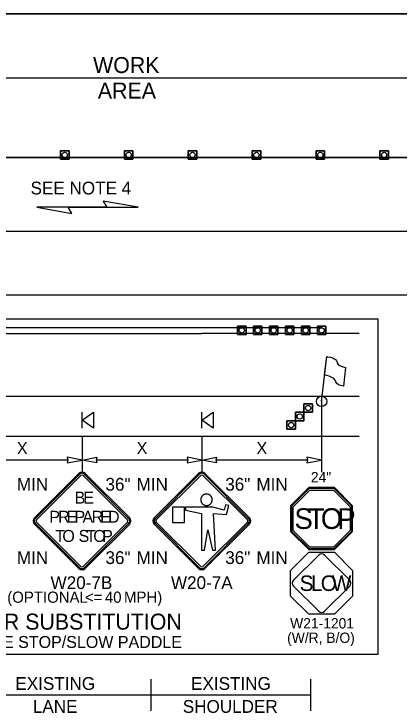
# Model space of a CAD drawing. Extents: x 99999.1 to 100095.7, y 99995 to 100010.7.
# Drawn here: x 100006.832 to 100009.243, y 100003.112 to 100007.492 of the extents above; entities that cross this region are included whole.
import ezdxf

# ---------------------------------------------------------------- set-up
doc = ezdxf.new("R2010")
doc.units = 0
for name, color, linetype in [('RD_ED_ShoulderPavedEdge', 7, 'Continuous'), ('RD_MK_LineDblYellowCenter', 7, 'Continuous'), ('RD_MK_LineEdgeWhite', 7, 'Continuous'), ('RD_MK_LineNoPass', 7, 'Continuous'), ('RD_MK_LineSkipCenter', 7, 'Continuous'), ('SH_DE_DetailHeading2Text', 7, 'Continuous'), ('TR_SN_ConstructionSigns', 7, 'Continuous'), ('TR_WZ_FlaggingStation', 7, 'Continuous'), ('TR_WZ_PortableSignMountBlk-Org', 7, 'Continuous'), ('TR_WZ_TrafficCone', 7, 'Continuous'), ('TR_WZ_WorkAreaLabel', 7, 'Continuous'), ('TR_WZ_WorkZoneDetails', 7, 'Continuous'), ('TR_WZ_WorkZoneTextCurrent', 7, 'Continuous')]:
    doc.layers.add(name, color=color, linetype=linetype)

msp = doc.modelspace()

# ---------------------------------------------------------------- linework, layer by layer
at = {"layer": 'RD_ED_ShoulderPavedEdge'}
for p, q in [((100000.1076, 100007.4923), (100015.6424, 100007.4923)), ((100000.1076, 100005.7323), (100015.6424, 100005.7323)), ((100005.4994, 100004.8473), (100008.9925, 100004.8473))]:
    msp.add_line(p, q, dxfattribs=at)
at = {"layer": 'RD_MK_LineDblYellowCenter'}
for p, q in [((100005.4994, 100005.5286), (100008.0081, 100005.5286)), ((100005.4994, 100005.4911), (100008.0081, 100005.4911))]:
    msp.add_line(p, q, dxfattribs=at)
at = {"layer": 'RD_MK_LineEdgeWhite'}
for p, q in [((100000.1076, 100007.0923), (100015.6424, 100007.0923)), ((100000.1076, 100006.1323), (100015.6424, 100006.1323)), ((100005.4994, 100005.0973), (100008.9925, 100005.0973))]:
    msp.add_line(p, q, dxfattribs=at)
at = {"layer": 'RD_MK_LineNoPass'}
msp.add_line((100008.0081, 100005.5286), (100008.7581, 100005.5286), dxfattribs=at)
at = {"layer": 'RD_MK_LineSkipCenter'}
for points in [[(100011.15, 100006.5923), (100003.4767, 100006.5923)], [(100008.9925, 100005.4911), (100008.0081, 100005.4911)]]:
    msp.add_lwpolyline(points, dxfattribs=at)
at = {"layer": 'TR_SN_ConstructionSigns'}
for p, q in [((100007.2382, 100004.6141), (100006.9598, 100004.3357)), ((100007.2437, 100004.6086), (100006.9653, 100004.3301)), ((100006.973, 100004.3224), (100007.2515, 100004.6008)), ((100007.2647, 100004.6008), (100007.5431, 100004.3224)), ((100007.5509, 100004.3301), (100007.2724, 100004.6086)), ((100007.5564, 100004.3357), (100007.278, 100004.6141)), ((100007.9882, 100004.6141), (100007.7098, 100004.3357)), ((100007.9937, 100004.6086), (100007.7153, 100004.3301)), ((100007.723, 100004.3224), (100008.0015, 100004.6008)), ((100008.0147, 100004.6008), (100008.2931, 100004.3224)), ((100008.3009, 100004.3301), (100008.0224, 100004.6086)), ((100008.3064, 100004.3357), (100008.028, 100004.6141)), ((100008.6775, 100004.5251), (100008.5636, 100004.4113)), ((100008.68, 100004.5191), (100008.5697, 100004.4087)), ((100008.5798, 100004.4046), (100008.6842, 100004.5089)), ((100008.8385, 100004.5251), (100008.6775, 100004.5251)), ((100008.836, 100004.5191), (100008.68, 100004.5191)), ((100008.6842, 100004.5089), (100008.8318, 100004.5089)), ((100008.8318, 100004.5089), (100008.9362, 100004.4046)), ((100008.9463, 100004.4087), (100008.836, 100004.5191)), ((100008.9524, 100004.4113), (100008.8385, 100004.5251)), ((100008.0015, 100004.4523), (100008.0013, 100004.4504)), ((100008.0013, 100004.4504), (100008.0013, 100004.4485)), ((100008.0013, 100004.4485), (100008.0013, 100004.4466)), ((100008.0013, 100004.4466), (100008.0015, 100004.4447)), ((100008.0017, 100004.4543), (100008.0015, 100004.4523)), ((100008.0021, 100004.4561), (100008.0017, 100004.4543)), ((100008.0025, 100004.458), (100008.0021, 100004.4561)), ((100008.0031, 100004.4598), (100008.0025, 100004.458)), ((100008.0037, 100004.4616), (100008.0031, 100004.4598)), ((100008.0045, 100004.4634), (100008.0037, 100004.4616)), ((100008.0053, 100004.4651), (100008.0045, 100004.4634)), ((100008.0062, 100004.4668), (100008.0053, 100004.4651)), ((100008.0073, 100004.4685), (100008.0062, 100004.4668)), ((100008.0083, 100004.47), (100008.0073, 100004.4685)), ((100008.0095, 100004.4715), (100008.0083, 100004.47)), ((100008.0108, 100004.473), (100008.0095, 100004.4715)), ((100008.0122, 100004.4743), (100008.0108, 100004.473)), ((100008.0135, 100004.4756), (100008.0122, 100004.4743)), ((100008.015, 100004.4768), (100008.0135, 100004.4756)), ((100008.0165, 100004.478), (100008.015, 100004.4768)), ((100008.0182, 100004.479), (100008.0165, 100004.478)), ((100008.0198, 100004.48), (100008.0182, 100004.479)), ((100008.0215, 100004.4809), (100008.0198, 100004.48)), ((100008.0232, 100004.4817), (100008.0215, 100004.4809)), ((100008.025, 100004.4824), (100008.0232, 100004.4817)), ((100008.0269, 100004.483), (100008.025, 100004.4824)), ((100008.0287, 100004.4835), (100008.0269, 100004.483)), ((100008.0306, 100004.4839), (100008.0287, 100004.4835)), ((100008.0325, 100004.4842), (100008.0306, 100004.4839)), ((100008.0344, 100004.4844), (100008.0325, 100004.4842)), ((100008.0363, 100004.4845), (100008.0344, 100004.4844)), ((100008.0382, 100004.4845), (100008.0363, 100004.4845)), ((100008.0401, 100004.4844), (100008.0382, 100004.4845)), ((100008.0421, 100004.4842), (100008.0401, 100004.4844)), ((100008.0439, 100004.4839), (100008.0421, 100004.4842)), ((100008.0458, 100004.4835), (100008.0439, 100004.4839)), ((100008.0476, 100004.483), (100008.0458, 100004.4835)), ((100008.0495, 100004.4824), (100008.0476, 100004.483)), ((100008.0513, 100004.4817), (100008.0495, 100004.4824)), ((100008.053, 100004.4809), (100008.0513, 100004.4817)), ((100008.0547, 100004.48), (100008.053, 100004.4809)), ((100008.0564, 100004.479), (100008.0547, 100004.48)), ((100008.058, 100004.478), (100008.0564, 100004.479)), ((100008.0595, 100004.4768), (100008.058, 100004.478)), ((100008.061, 100004.4756), (100008.0595, 100004.4768)), ((100008.0624, 100004.4743), (100008.061, 100004.4756)), ((100008.0637, 100004.473), (100008.0624, 100004.4743)), ((100008.065, 100004.4715), (100008.0637, 100004.473)), ((100008.0661, 100004.47), (100008.065, 100004.4715)), ((100008.0673, 100004.4685), (100008.0661, 100004.47)), ((100008.0683, 100004.4668), (100008.0673, 100004.4685)), ((100008.0692, 100004.4651), (100008.0683, 100004.4668)), ((100008.07, 100004.4634), (100008.0692, 100004.4651)), ((100008.0708, 100004.4616), (100008.07, 100004.4634)), ((100008.0715, 100004.4598), (100008.0708, 100004.4616)), ((100008.072, 100004.458), (100008.0715, 100004.4598)), ((100008.0725, 100004.4561), (100008.072, 100004.458)), ((100008.0728, 100004.4543), (100008.0725, 100004.4561)), ((100008.0731, 100004.4523), (100008.0728, 100004.4543)), ((100008.0732, 100004.4504), (100008.0731, 100004.4523)), ((100008.0731, 100004.4447), (100008.0732, 100004.4466)), ((100008.0733, 100004.4485), (100008.0732, 100004.4504)), ((100008.0732, 100004.4466), (100008.0733, 100004.4485)), ((100008.0015, 100004.4447), (100008.0017, 100004.4428)), ((100008.0017, 100004.4428), (100008.0021, 100004.4409)), ((100008.0021, 100004.4409), (100008.0025, 100004.439)), ((100008.0025, 100004.439), (100008.0031, 100004.4372)), ((100008.0031, 100004.4372), (100008.0037, 100004.4354)), ((100008.0037, 100004.4354), (100008.0045, 100004.4336)), ((100008.0045, 100004.4336), (100008.0053, 100004.4319)), ((100008.0053, 100004.4319), (100008.0062, 100004.4302)), ((100008.0062, 100004.4302), (100008.0073, 100004.4286)), ((100008.0073, 100004.4286), (100008.0083, 100004.427)), ((100008.0083, 100004.427), (100008.0095, 100004.4255)), ((100008.0095, 100004.4255), (100008.0108, 100004.4241)), ((100008.0108, 100004.4241), (100008.0122, 100004.4227)), ((100008.0122, 100004.4227), (100008.0135, 100004.4214)), ((100008.0135, 100004.4214), (100008.015, 100004.4202)), ((100008.015, 100004.4202), (100008.0165, 100004.419)), ((100008.0165, 100004.419), (100008.0182, 100004.418)), ((100008.0182, 100004.418), (100008.0198, 100004.417)), ((100008.0198, 100004.417), (100008.0215, 100004.4161)), ((100008.0215, 100004.4161), (100008.0232, 100004.4153)), ((100008.0232, 100004.4153), (100008.025, 100004.4146)), ((100008.025, 100004.4146), (100008.0269, 100004.414)), ((100008.0269, 100004.414), (100008.0287, 100004.4135)), ((100008.0287, 100004.4135), (100008.0306, 100004.4131)), ((100008.0306, 100004.4131), (100008.0325, 100004.4128)), ((100008.0325, 100004.4128), (100008.0344, 100004.4126)), ((100008.0344, 100004.4126), (100008.0363, 100004.4125)), ((100008.0363, 100004.4125), (100008.0382, 100004.4125)), ((100008.0382, 100004.4125), (100008.0401, 100004.4126)), ((100008.0401, 100004.4126), (100008.0421, 100004.4128)), ((100008.0421, 100004.4128), (100008.0439, 100004.4131)), ((100008.0439, 100004.4131), (100008.0458, 100004.4135)), ((100008.0458, 100004.4135), (100008.0476, 100004.414)), ((100008.0476, 100004.414), (100008.0495, 100004.4146)), ((100008.0495, 100004.4146), (100008.0513, 100004.4153)), ((100008.0513, 100004.4153), (100008.053, 100004.4161)), ((100008.053, 100004.4161), (100008.0547, 100004.417)), ((100008.0547, 100004.417), (100008.0564, 100004.418)), ((100008.0564, 100004.418), (100008.058, 100004.419)), ((100008.058, 100004.419), (100008.0595, 100004.4202)), ((100008.0595, 100004.4202), (100008.061, 100004.4214)), ((100008.061, 100004.4214), (100008.0624, 100004.4227)), ((100008.0624, 100004.4227), (100008.0637, 100004.4241)), ((100008.0637, 100004.4241), (100008.065, 100004.4255)), ((100008.065, 100004.4255), (100008.0661, 100004.427)), ((100008.0661, 100004.427), (100008.0673, 100004.4286)), ((100008.0673, 100004.4286), (100008.0683, 100004.4302)), ((100008.0683, 100004.4302), (100008.0692, 100004.4319)), ((100008.0692, 100004.4319), (100008.07, 100004.4336)), ((100008.07, 100004.4336), (100008.0708, 100004.4354)), ((100008.0708, 100004.4354), (100008.0715, 100004.4372)), ((100008.0715, 100004.4372), (100008.072, 100004.439)), ((100008.072, 100004.439), (100008.0725, 100004.4409)), ((100008.0725, 100004.4409), (100008.0728, 100004.4428)), ((100008.0728, 100004.4428), (100008.0731, 100004.4447)), ((100008.1568, 100004.4169), (100008.1471, 100004.3841)), ((100008.1767, 100004.4133), (100008.1568, 100004.4169)), ((100008.1617, 100004.3565), (100008.1767, 100004.4133)), ((100008.5636, 100004.4113), (100008.5636, 100004.2502)), ((100008.5697, 100004.4087), (100008.5697, 100004.2527)), ((100008.5798, 100004.2569), (100008.5798, 100004.4046)), ((100008.9362, 100004.4046), (100008.9362, 100004.2569)), ((100008.9463, 100004.2527), (100008.9463, 100004.4087)), ((100008.9524, 100004.2502), (100008.9524, 100004.4113)), ((100007.8238, 100004.4012), (100007.8238, 100004.3065)), ((100007.8992, 100004.4012), (100007.8238, 100004.4012)), ((100007.8992, 100004.3065), (100007.8992, 100004.4012)), ((100008.0775, 100004.4012), (100007.9062, 100004.4012)), ((100007.9062, 100004.4012), (100007.9062, 100004.3831)), ((100007.9062, 100004.3831), (100008.0057, 100004.3633)), ((100008.0057, 100004.3633), (100008.0057, 100004.133)), ((100008.1471, 100004.3841), (100008.0775, 100004.4012)), ((100008.0938, 100004.133), (100008.0807, 100004.3634)), ((100008.0807, 100004.3634), (100008.1617, 100004.3565)), ((100006.9598, 100004.2959), (100007.2382, 100004.0175)), ((100006.9653, 100004.3014), (100007.2437, 100004.023)), ((100007.2515, 100004.0307), (100006.973, 100004.3092)), ((100007.5431, 100004.3092), (100007.2647, 100004.0307)), ((100007.2724, 100004.023), (100007.5509, 100004.3014)), ((100007.278, 100004.0175), (100007.5564, 100004.2959)), ((100007.7098, 100004.2959), (100007.9882, 100004.0175)), ((100007.7153, 100004.3014), (100007.9937, 100004.023)), ((100008.0015, 100004.0307), (100007.723, 100004.3092)), ((100007.8238, 100004.3065), (100007.8992, 100004.3065)), ((100008.2931, 100004.3092), (100008.0147, 100004.0307)), ((100008.0224, 100004.023), (100008.3009, 100004.3014)), ((100008.028, 100004.0175), (100008.3064, 100004.2959)), ((100008.0259, 100004.133), (100008.0455, 100004.2597)), ((100008.0455, 100004.2597), (100008.0758, 100004.133)), ((100008.5636, 100004.2502), (100008.6775, 100004.1363)), ((100008.5697, 100004.2527), (100008.68, 100004.1424)), ((100008.6842, 100004.1525), (100008.5798, 100004.2569)), ((100008.9362, 100004.2569), (100008.8318, 100004.1525)), ((100008.836, 100004.1424), (100008.9463, 100004.2527)), ((100008.8385, 100004.1363), (100008.9524, 100004.2502)), ((100008.68, 100004.1424), (100008.836, 100004.1424)), ((100008.8318, 100004.1525), (100008.6842, 100004.1525)), ((100008.0057, 100004.133), (100008.0259, 100004.133)), ((100008.0758, 100004.133), (100008.0938, 100004.133)), ((100008.7397, 100004.1018), (100008.5819, 100003.9441)), ((100008.6775, 100004.1363), (100008.8385, 100004.1363)), ((100008.9341, 100003.9441), (100008.7763, 100004.1018)), ((100008.5819, 100003.9074), (100008.7397, 100003.7497)), ((100008.7763, 100003.7497), (100008.9341, 100003.9074))]:
    msp.add_line(p, q, dxfattribs=at)
msp.add_lwpolyline([(100008.9524, 100004.0063), (100008.9524, 100003.8452), (100008.8385, 100003.7313), (100008.6775, 100003.7313), (100008.5636, 100003.8452), (100008.5636, 100004.0063), (100008.6775, 100004.1201), (100008.8385, 100004.1201)], close=True, dxfattribs=at)
for centre, radius, start, end in [((100007.2581, 100004.5942), 0.0281, 45, 135), ((100008.0081, 100004.5942), 0.0281, 45, 135), ((100007.2581, 100004.5942), 0.0203, 45, 135), ((100007.2581, 100004.5942), 0.00937, 45, 135), ((100008.0081, 100004.5942), 0.0203, 45, 135), ((100008.0081, 100004.5942), 0.00937, 45, 135), ((100006.9797, 100004.3158), 0.0281, 135, 225), ((100006.9797, 100004.3158), 0.0203, 135, 225), ((100006.9797, 100004.3158), 0.00937, 135, 225), ((100007.5365, 100004.3158), 0.00937, 315, 45), ((100007.5365, 100004.3158), 0.0203, 315, 45), ((100007.5365, 100004.3158), 0.0281, 315, 45), ((100007.7297, 100004.3158), 0.0281, 135, 225), ((100007.7297, 100004.3158), 0.0203, 135, 225), ((100007.7297, 100004.3158), 0.00937, 135, 225), ((100008.2865, 100004.3158), 0.00937, 315, 45), ((100008.2865, 100004.3158), 0.0203, 315, 45), ((100008.2865, 100004.3158), 0.0281, 315, 45), ((100008.758, 100004.0835), 0.0259, 45, 135), ((100007.2581, 100004.0374), 0.0281, 225, 315), ((100007.2581, 100004.0374), 0.0203, 225, 315), ((100007.2581, 100004.0374), 0.00937, 225, 315), ((100008.0081, 100004.0374), 0.0281, 225, 315), ((100008.0081, 100004.0374), 0.0203, 225, 315), ((100008.0081, 100004.0374), 0.00937, 225, 315), ((100008.6003, 100003.9257), 0.0259, 135, 225), ((100008.9157, 100003.9257), 0.0259, 315, 45), ((100008.758, 100003.768), 0.0259, 225, 315)]:
    msp.add_arc(centre, radius, start, end, dxfattribs=at)
at = {"layer": 'TR_WZ_FlaggingStation'}
for p, q in [((100008.7581, 100005.0648), (100008.7901, 100005.3458)), ((100008.7771, 100005.2317), (100008.7902, 100005.3461)), ((100008.9081, 100005.2783), (100008.8948, 100005.1611)), ((100008.7771, 100005.2317), (100008.7771, 100005.2317))]:
    msp.add_line(p, q, dxfattribs=at)
for points in [[(100008.7902, 100005.3461), (100008.7959, 100005.3448), (100008.8137, 100005.3414), (100008.8276, 100005.3372), (100008.8372, 100005.3311), (100008.8458, 100005.3264), (100008.8515, 100005.3196), (100008.8557, 100005.3117), (100008.8562, 100005.3055), (100008.8616, 100005.2963), (100008.8724, 100005.2889), (100008.8848, 100005.2837), (100008.9081, 100005.2783)], [(100008.8948, 100005.1611), (100008.8867, 100005.1625), (100008.869, 100005.1671), (100008.8533, 100005.1776), (100008.8468, 100005.1882), (100008.8429, 100005.1985), (100008.8338, 100005.2094), (100008.8229, 100005.2156), (100008.8055, 100005.2227), (100008.7771, 100005.2317)]]:
    msp.add_lwpolyline(points, dxfattribs=at)
msp.add_circle((100008.7581, 100005.0648), 0.0325, dxfattribs=at)
at = {"layer": 'TR_WZ_PortableSignMountBlk-Org'}
for p, q in [((100007.2581, 100004.8974), (100007.2581, 100004.9974)), ((100008.0081, 100004.8974), (100008.0081, 100004.9974))]:
    msp.add_line(p, q, dxfattribs=at)
for points in [[(100007.2581, 100004.9473), (100007.3299, 100004.9974), (100007.3299, 100004.8974)], [(100008.0081, 100004.9473), (100008.0799, 100004.9974), (100008.0799, 100004.8974)]]:
    msp.add_lwpolyline(points, close=True, dxfattribs=at)
at = {"layer": 'TR_WZ_TrafficCone'}
for points in [[(100007.1234, 100006.6357), (100007.1767, 100006.6357), (100007.1767, 100006.5823), (100007.1234, 100006.5823), (100007.1234, 100006.6357)], [(100007.1234, 100006.5823), (100007.1767, 100006.5823), (100007.1767, 100006.6357), (100007.1234, 100006.6357), (100007.1234, 100006.5823)], [(100007.5234, 100006.6357), (100007.5767, 100006.6357), (100007.5767, 100006.5823), (100007.5234, 100006.5823), (100007.5234, 100006.6357)], [(100007.5234, 100006.5823), (100007.5767, 100006.5823), (100007.5767, 100006.6357), (100007.5234, 100006.6357), (100007.5234, 100006.5823)], [(100007.9234, 100006.6357), (100007.9767, 100006.6357), (100007.9767, 100006.5823), (100007.9234, 100006.5823), (100007.9234, 100006.6357)], [(100007.9234, 100006.5823), (100007.9767, 100006.5823), (100007.9767, 100006.6357), (100007.9234, 100006.6357), (100007.9234, 100006.5823)], [(100008.3234, 100006.6357), (100008.3767, 100006.6357), (100008.3767, 100006.5823), (100008.3234, 100006.5823), (100008.3234, 100006.6357)], [(100008.3234, 100006.5823), (100008.3767, 100006.5823), (100008.3767, 100006.6357), (100008.3234, 100006.6357), (100008.3234, 100006.5823)], [(100008.7234, 100006.6357), (100008.7767, 100006.6357), (100008.7767, 100006.5823), (100008.7234, 100006.5823), (100008.7234, 100006.6357)], [(100008.7234, 100006.5823), (100008.7767, 100006.5823), (100008.7767, 100006.6357), (100008.7234, 100006.6357), (100008.7234, 100006.5823)], [(100009.1234, 100006.6357), (100009.1767, 100006.6357), (100009.1767, 100006.5823), (100009.1234, 100006.5823), (100009.1234, 100006.6357)], [(100009.1234, 100006.5823), (100009.1767, 100006.5823), (100009.1767, 100006.6357), (100009.1234, 100006.6357), (100009.1234, 100006.5823)], [(100008.2848, 100005.5365), (100008.2314, 100005.5365), (100008.2314, 100005.4832), (100008.2848, 100005.4832), (100008.2848, 100005.5365)], [(100008.2848, 100005.4832), (100008.2314, 100005.4832), (100008.2314, 100005.5365), (100008.2848, 100005.5365), (100008.2848, 100005.4832)], [(100008.3848, 100005.5365), (100008.3314, 100005.5365), (100008.3314, 100005.4832), (100008.3848, 100005.4832), (100008.3848, 100005.5365)], [(100008.3848, 100005.4832), (100008.3314, 100005.4832), (100008.3314, 100005.5365), (100008.3848, 100005.5365), (100008.3848, 100005.4832)], [(100008.4848, 100005.5365), (100008.4314, 100005.5365), (100008.4314, 100005.4832), (100008.4848, 100005.4832), (100008.4848, 100005.5365)], [(100008.4848, 100005.4832), (100008.4314, 100005.4832), (100008.4314, 100005.5365), (100008.4848, 100005.5365), (100008.4848, 100005.4832)], [(100008.5848, 100005.5365), (100008.5314, 100005.5365), (100008.5314, 100005.4832), (100008.5848, 100005.4832), (100008.5848, 100005.5365)], [(100008.5848, 100005.4832), (100008.5314, 100005.4832), (100008.5314, 100005.5365), (100008.5848, 100005.5365), (100008.5848, 100005.4832)], [(100008.6848, 100005.5365), (100008.6314, 100005.5365), (100008.6314, 100005.4832), (100008.6848, 100005.4832), (100008.6848, 100005.5365)], [(100008.6848, 100005.4832), (100008.6314, 100005.4832), (100008.6314, 100005.5365), (100008.6848, 100005.5365), (100008.6848, 100005.4832)], [(100008.7848, 100005.5365), (100008.7314, 100005.5365), (100008.7314, 100005.4832), (100008.7848, 100005.4832), (100008.7848, 100005.5365)], [(100008.7848, 100005.4832), (100008.7314, 100005.4832), (100008.7314, 100005.5365), (100008.7848, 100005.5365), (100008.7848, 100005.4832)], [(100008.6474, 100005.05), (100008.7008, 100005.05), (100008.7008, 100004.9967), (100008.6474, 100004.9967), (100008.6474, 100005.05)], [(100008.6474, 100004.9967), (100008.7008, 100004.9967), (100008.7008, 100005.05), (100008.6474, 100005.05), (100008.6474, 100004.9967)], [(100008.5941, 100004.9967), (100008.6474, 100004.9967), (100008.6474, 100004.9433), (100008.5941, 100004.9433), (100008.5941, 100004.9967)], [(100008.5941, 100004.9433), (100008.6474, 100004.9433), (100008.6474, 100004.9967), (100008.5941, 100004.9967), (100008.5941, 100004.9433)], [(100008.5408, 100004.9433), (100008.5941, 100004.9433), (100008.5941, 100004.89), (100008.5408, 100004.89), (100008.5408, 100004.9433)], [(100008.5408, 100004.89), (100008.5941, 100004.89), (100008.5941, 100004.9433), (100008.5408, 100004.9433), (100008.5408, 100004.89)]]:
    msp.add_lwpolyline(points, dxfattribs=at)
for centre in [(100007.15, 100006.609), (100007.55, 100006.609), (100007.95, 100006.609), (100008.35, 100006.609), (100008.75, 100006.609), (100009.15, 100006.609), (100008.2581, 100005.5098), (100008.3581, 100005.5098), (100008.4581, 100005.5098), (100008.5581, 100005.5098), (100008.6581, 100005.5098), (100008.7581, 100005.5098), (100008.6741, 100005.0233), (100008.6208, 100004.97), (100008.5674, 100004.9167)]:
    msp.add_circle(centre, 0.0167, dxfattribs=at)
at = {"layer": 'TR_WZ_WorkZoneDetails'}
for p, q in [((100007.1713, 100006.2816), (100007.4124, 100006.2816)), ((100007.4124, 100006.2816), (100007.1713, 100006.2816)), ((100008.7581, 100005.0973), (100008.7581, 100004.6223)), ((100007.2581, 100004.8473), (100007.2581, 100004.6223)), ((100008.0081, 100004.8473), (100008.0081, 100004.6223)), ((100007.1702, 100004.6973), (100006.596, 100004.6973)), ((100007.9202, 100004.6973), (100007.346, 100004.6973)), ((100008.6702, 100004.6973), (100008.096, 100004.6973)), ((100007.6907, 100003.1255), (100007.6907, 100003.3255)), ((100008.6907, 100003.1255), (100008.6907, 100003.3255)), ((100006.4907, 100003.2255), (100007.6907, 100003.2255)), ((100007.6907, 100003.2255), (100008.6907, 100003.2255))]:
    msp.add_line(p, q, dxfattribs=at)
for points in [[(100005.15, 100007.4923), (100005.15, 100006.5923), (100009.9338, 100006.5923), (100009.9338, 100007.4923)], [(100007.609, 100006.2816), (100007.3901, 100006.3202), (100007.4124, 100006.2816)], [(100006.9748, 100006.2816), (100007.1936, 100006.243), (100007.1713, 100006.2816)], [(100007.2581, 100004.6973), (100007.1659, 100004.7154), (100007.1702, 100004.6973), (100007.1659, 100004.6793)], [(100007.2581, 100004.6973), (100007.3502, 100004.7154), (100007.346, 100004.6973), (100007.3502, 100004.6793)], [(100008.0081, 100004.6973), (100007.9159, 100004.7154), (100007.9202, 100004.6973), (100007.9159, 100004.6793)], [(100008.0081, 100004.6973), (100008.1002, 100004.7154), (100008.096, 100004.6973), (100008.1002, 100004.6793)], [(100008.7581, 100004.6973), (100008.6659, 100004.7154), (100008.6702, 100004.6973), (100008.6659, 100004.6793)]]:
    msp.add_lwpolyline(points, close=True, dxfattribs=at)
at = {"layer": 'TR_WZ_WorkZoneTextCurrent'}
msp.add_lwpolyline([(100005.3092, 100005.5823), (100009.1102, 100005.5823), (100009.1102, 100003.4799), (100005.3092, 100003.4799)], close=True, dxfattribs=at)

# ---------------------------------------------------------------- texts
at = {"layer": 'SH_DE_DetailHeading2Text'}
msp.add_text('HUMAN FLAGGER SUBSTITUTION', height=0.1, rotation=360, dxfattribs=at).set_placement((100005.6986, 100003.6349))
at = {"layer": 'TR_SN_ConstructionSigns'}
for s, height, p in [('24"', 0.0648, (100008.6908, 100004.5575)), ('B', 0.075, (100007.2118, 100004.4243)), ('E', 0.075, (100007.2661, 100004.4243)), ('P', 0.075, (100007.0532, 100004.3043)), ('R', 0.075, (100007.1084, 100004.3043)), ('E', 0.075, (100007.1616, 100004.3043)), ('P', 0.075, (100007.2111, 100004.3043)), ('A', 0.075, (100007.261, 100004.3043)), ('R', 0.075, (100007.3183, 100004.3043)), ('E', 0.075, (100007.3715, 100004.3043)), ('D', 0.075, (100007.421, 100004.3043)), ('S', 0.1296, (100008.5876, 100004.2659)), ('T', 0.1296, (100008.6718, 100004.2659)), ('O', 0.1296, (100008.7535, 100004.2659)), ('P', 0.1296, (100008.8559, 100004.2659)), ('T', 0.075, (100007.0898, 100004.1843)), ('O', 0.075, (100007.135, 100004.1843)), ('S', 0.075, (100007.2364, 100004.1843)), ('T', 0.075, (100007.2835, 100004.1843)), ('O', 0.075, (100007.3286, 100004.1843)), ('P', 0.075, (100007.3843, 100004.1843)), ('S', 0.0972, (100008.6205, 100003.8771)), ('L', 0.0972, (100008.6914, 100003.8771)), ('O', 0.0972, (100008.7527, 100003.8771)), ('W', 0.0972, (100008.8217, 100003.8771))]:
    msp.add_text(s, height=height, dxfattribs=at).set_placement(p)
for s, height, p in [('MIN', 0.08, (100006.8499, 100004.5056)), ('36"', 0.08, (100007.4048, 100004.5056)), ('MIN', 0.08, (100007.5999, 100004.5056)), ('36"', 0.08, (100008.1548, 100004.5056)), ('MIN', 0.08, (100008.3499, 100004.5056)), ('MIN', 0.08, (100006.8499, 100004.046)), ('36"', 0.08, (100007.4048, 100004.046)), ('MIN', 0.08, (100007.5999, 100004.046)), ('36"', 0.08, (100008.1548, 100004.046)), ('MIN', 0.08, (100008.3499, 100004.046)), ('W20-7B', 0.08, (100007.0611, 100003.8892)), ('W20-7A', 0.08, (100007.8148, 100003.8892)), ('(OPTIONAL', 0.07, (100006.79, 100003.8032)), ('MPH)', 0.07, (100007.521, 100003.8032)), ('<=', 0.07, (100007.2763, 100003.8032)), ('40', 0.07, (100007.4013, 100003.8032)), ('W21-1201', 0.0648, (100008.5611, 100003.6422)), ('(W/R, B/O)', 0.0648, (100008.5423, 100003.5515))]:
    msp.add_text(s, height=height, rotation=360, dxfattribs=at).set_placement(p)
at = {"layer": 'TR_WZ_WorkAreaLabel'}
for s, p in [('WORK', (100007.3273, 100007.1223)), ('AREA', (100007.357, 100006.9623))]:
    msp.add_text(s, height=0.1, dxfattribs=at).set_placement(p)
at = {"layer": 'TR_WZ_WorkZoneDetails'}
for s, p in [('EXISTING', (100006.8409, 100003.2575)), ('EXISTING', (100007.9409, 100003.2575)), ('LANE', (100006.9503, 100003.1135)), ('SHOULDER', (100007.889, 100003.1135))]:
    msp.add_text(s, height=0.08, rotation=360, dxfattribs=at).set_placement(p)
at = {"layer": 'TR_WZ_WorkZoneTextCurrent'}
for s, height, p in [('SEE NOTE 4', 0.08, (100006.9359, 100006.3616)), ('UPDATE SIGNAGE & USE STOP/SLOW PADDLE', 0.075, (100005.6099, 100003.5199))]:
    msp.add_text(s, height=height, dxfattribs=at).set_placement(p)
for p in [(100006.8505, 100004.7348), (100007.6005, 100004.7348), (100008.3505, 100004.7348)]:
    msp.add_text('X', height=0.075, rotation=360, dxfattribs=at).set_placement(p)

doc.saveas('drawing.dxf')
